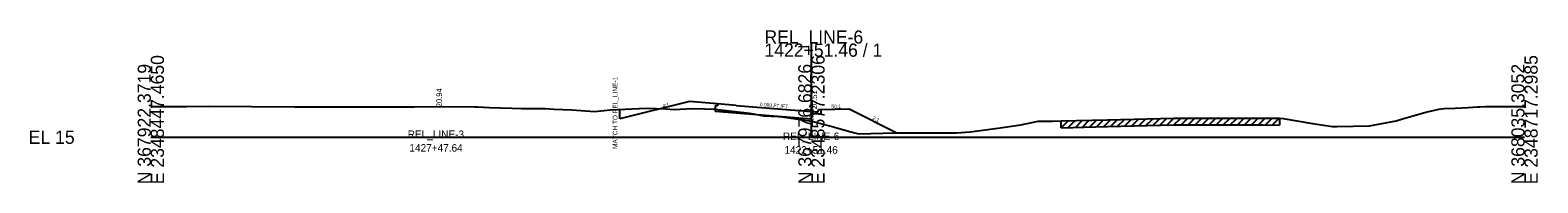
# Model space of a CAD drawing. Extents: x -26 to 403, y -10 to 6565.
# Drawn here: x -25.7 to 295.4, y 3490.3 to 3522.8 of the extents above; entities that cross this region are included whole.
import ezdxf

# ---------------------------------------------------------------- set-up
doc = ezdxf.new("R2010")
doc.units = 0
for name, color, linetype in [('RD_GPK_XS_Cell', 7, 'Continuous'), ('RD_XS_Base', 7, 'Continuous'), ('RD_XS_CurbBase', 7, 'Continuous'), ('RD_XS_CurbFront', 7, 'Continuous'), ('RD_XS_CurbTop', 7, 'Continuous'), ('RD_XS_EarthShd', 7, 'Continuous'), ('RD_XS_ExGround', 7, 'Continuous'), ('RD_XS_ExPaveRet', 7, 'Continuous'), ('RD_XS_Pave', 7, 'Continuous'), ('RD_XS_PaveShd', 7, 'Continuous'), ('RD_XS_TieSlope', 7, 'Continuous'), ('RD_XS_TX_Elev_EX', 7, 'Continuous'), ('RD_XS_TX_Elev_PR', 7, 'Continuous'), ('RD_XS_TX_MatchLine', 7, 'Continuous'), ('RD_XS_TX_Slope', 7, 'Continuous'), ('RD_XS_TX_Station', 7, 'Continuous'), ('RD_XS_TX_TOC', 7, 'Continuous')]:
    doc.layers.add(name, color=color, linetype=linetype)

msp = doc.modelspace()

# ---------------------------------------------------------------- linework, layer by layer
at = {"layer": 'RD_GPK_XS_Cell'}
for p, q in [((140.67, 3500), (140.67, 3519.94)), ((0, 3500), (140.67, 3500)), ((140.67, 3500), (292.51, 3500))]:
    msp.add_line(p, q, dxfattribs=at)
at = {"layer": 'RD_XS_Base'}
for p, q in [((120.68, 3506.66), (120.18, 3506.7)), ((120.18, 3506.7), (120.18, 3505.51)), ((120.68, 3507.11), (120.68, 3506.66)), ((140.68, 3503.87), (120.18, 3505.51))]:
    msp.add_line(p, q, dxfattribs=at)
at = {"layer": 'RD_XS_CurbBase'}
for p, q in [((142.68, 3505.91), (142.68, 3504.91)), ((142.18, 3504.91), (140.68, 3504.99)), ((140.68, 3503.87), (140.68, 3504.99)), ((142.68, 3504.91), (142.18, 3504.91))]:
    msp.add_line(p, q, dxfattribs=at)
at = {"layer": 'RD_XS_CurbFront'}
msp.add_line((140.68, 3504.99), (140.68, 3505.49), dxfattribs=at)
at = {"layer": 'RD_XS_CurbTop'}
for p, q in [((142.1, 3505.41), (142.18, 3505.91)), ((142.18, 3505.91), (142.68, 3505.91)), ((140.68, 3505.51), (140.68, 3505.49)), ((140.68, 3505.49), (142.1, 3505.41))]:
    msp.add_line(p, q, dxfattribs=at)
at = {"layer": 'RD_XS_EarthShd'}
for p, q in [((114.68, 3507.59), (99.9, 3503.9)), ((120.68, 3507.11), (114.68, 3507.59)), ((142.68, 3505.91), (148.68, 3506.03))]:
    msp.add_line(p, q, dxfattribs=at)
at = {"layer": 'RD_XS_ExGround'}
msp.add_lwpolyline([(0, 3506.57), (3.29, 3506.58), (7.51, 3506.58), (12.39, 3506.65), (30.61, 3506.5), (46.58, 3506.5), (56.1, 3506.5), (64.62, 3506.52), (68.97, 3506.44), (69.6, 3506.44), (72.07, 3506.34), (76.86, 3506.21), (78.95, 3506.1), (82.99, 3506.09), (83.98, 3506.09), (85.91, 3505.96), (89.66, 3505.83), (94.52, 3505.49), (97.78, 3505.83), (105.53, 3506.2), (109.7, 3506.04), (111.45, 3505.9), (115.28, 3506.09), (117.96, 3506.08), (120.1, 3505.98), (127.51, 3505.1), (130.56, 3504.58), (133.69, 3504.42), (134.41, 3504.36), (140.19, 3503.52), (140.67, 3503.41), (145.08, 3502.32), (149.07, 3501.13), (150.79, 3500.73), (158.41, 3500.93), (168.47, 3500.91), (171.59, 3500.91), (174.45, 3501.14), (180.34, 3501.92), (185.24, 3502.61), (188.95, 3503.41), (191.98, 3503.43), (193.87, 3503.48), (203.75, 3503.71), (217.86, 3504.07), (236.71, 3504.05), (240.33, 3504.04), (241.15, 3503.96), (247.4, 3502.95), (251.65, 3502.29), (252.63, 3502.32), (259.51, 3502.4), (265.15, 3503.49), (266.53, 3503.91), (271.48, 3505.34), (273.03, 3505.72), (274.27, 3505.99), (275.94, 3506.19), (276.39, 3506.14), (280.55, 3506.35), (282.49, 3506.44), (283, 3506.49), (284.23, 3506.55), (289.14, 3506.56), (292.1, 3506.53), (292.51, 3506.52)], dxfattribs=at)
at = {"layer": 'RD_XS_ExPaveRet'}
for p, q in [((193.87, 3502.04), (195.34, 3503.51)), ((193.87, 3502.04), (193.87, 3503.48)), ((195.37, 3502.08), (196.84, 3503.55)), ((196.87, 3502.11), (198.34, 3503.58)), ((198.37, 3502.15), (199.84, 3503.62)), ((199.87, 3502.18), (201.34, 3503.65)), ((201.37, 3502.22), (202.84, 3503.69)), ((202.87, 3502.25), (204.34, 3503.72)), ((203.75, 3502.27), (217.86, 3502.63)), ((204.37, 3502.29), (205.85, 3503.76)), ((205.87, 3502.33), (207.35, 3503.8)), ((207.37, 3502.36), (208.85, 3503.84)), ((208.87, 3502.4), (210.35, 3503.88)), ((210.37, 3502.44), (211.85, 3503.91)), ((211.87, 3502.48), (213.35, 3503.95)), ((213.37, 3502.52), (214.85, 3503.99)), ((214.87, 3502.55), (216.35, 3504.03)), ((216.37, 3502.59), (217.85, 3504.07)), ((217.86, 3502.63), (236.71, 3502.62)), ((217.87, 3502.63), (219.31, 3504.07)), ((219.37, 3502.63), (220.81, 3504.07)), ((220.87, 3502.63), (222.31, 3504.07)), ((222.37, 3502.63), (223.81, 3504.06)), ((223.87, 3502.63), (225.31, 3504.06)), ((225.37, 3502.63), (226.81, 3504.06)), ((226.87, 3502.62), (228.31, 3504.06)), ((228.37, 3502.62), (229.81, 3504.06)), ((229.87, 3502.62), (231.31, 3504.06)), ((231.37, 3502.62), (232.81, 3504.06)), ((232.87, 3502.62), (234.31, 3504.06)), ((234.37, 3502.62), (235.81, 3504.06)), ((235.87, 3502.62), (237.31, 3504.05)), ((236.71, 3502.62), (240.33, 3502.6)), ((237.37, 3502.61), (238.8, 3504.05)), ((238.87, 3502.61), (240.3, 3504.04)), ((240.33, 3504.04), (240.33, 3502.6)), ((193.87, 3502.04), (203.75, 3502.27))]:
    msp.add_line(p, q, dxfattribs=at)
at = {"layer": 'RD_XS_Pave'}
for p, q in [((99.9, 3503.9), (99.9, 3505.93)), ((124.68, 3506.79), (140.68, 3505.51))]:
    msp.add_line(p, q, dxfattribs=at)
at = {"layer": 'RD_XS_PaveShd'}
msp.add_line((124.68, 3506.79), (120.68, 3507.11), dxfattribs=at)
at = {"layer": 'RD_XS_TieSlope'}
msp.add_line((148.68, 3506.03), (158.87, 3500.93), dxfattribs=at)

# ---------------------------------------------------------------- texts
at = {"layer": 'RD_GPK_XS_Cell'}
for s, p in [('REL_LINE-6', (130.67, 3519.94)), ('1422+51.46 / 1', (130.67, 3517.14)), ('EL 15', (-26, 3498.6))]:
    msp.add_text(s, height=2.8, dxfattribs=at).set_placement(p)
for s, p in [('E 2348447.4650', (2.8, 3490)), ('E 2348577.2306', (143.47, 3490)), ('E 2348717.2985', (295.31, 3490)), ('N 367922.3719', (0, 3490)), ('N 367976.6826', (140.67, 3490)), ('N 368035.3052', (292.51, 3490))]:
    msp.add_text(s, height=2.8, rotation=90, dxfattribs=at).set_placement(p)
at = {"layer": 'RD_XS_TX_Elev_EX'}
msp.add_text('18.41', height=1, rotation=90, dxfattribs=at).set_placement((141.17, 3503.41))
at = {"layer": 'RD_XS_TX_Elev_PR'}
for s, p in [(' 20.94', (62, 3505.94)), (' 20.51', (141.87, 3505.51))]:
    msp.add_text(s, height=1.2, rotation=90, dxfattribs=at).set_placement(p)
at = {"layer": 'RD_XS_TX_MatchLine'}
msp.add_text('MATCH TO REL_LINE-1', height=1, rotation=90, dxfattribs=at).set_placement((99.36, 3497.51))
at = {"layer": 'RD_XS_TX_Slope'}
for s, rotation, p in [('4:1', 14.0362, (109.06, 3506.25)), ('0.080 FT./FT.', 355.4291, (129.68, 3506.64)), ('50:1', 1.1458, (144.91, 3506.15)), ('2:1', 333.4349, (153.62, 3503.86))]:
    msp.add_text(s, height=0.75, rotation=rotation, dxfattribs=at).set_placement(p)
at = {"layer": 'RD_XS_TX_Station'}
for s, p in [('REL_LINE-3', (54.7, 3499.84)), ('REL_LINE-6', (134.59, 3499.41)), ('1427+47.64', (55.06, 3496.94)), ('1422+51.46', (134.92, 3496.51))]:
    msp.add_text(s, height=1.6, dxfattribs=at).set_placement(p)
at = {"layer": 'RD_XS_TX_TOC'}
msp.add_text('TOCRT', height=0.05, dxfattribs=at).set_placement((141.9, 3505.86))

doc.saveas('drawing.dxf')
